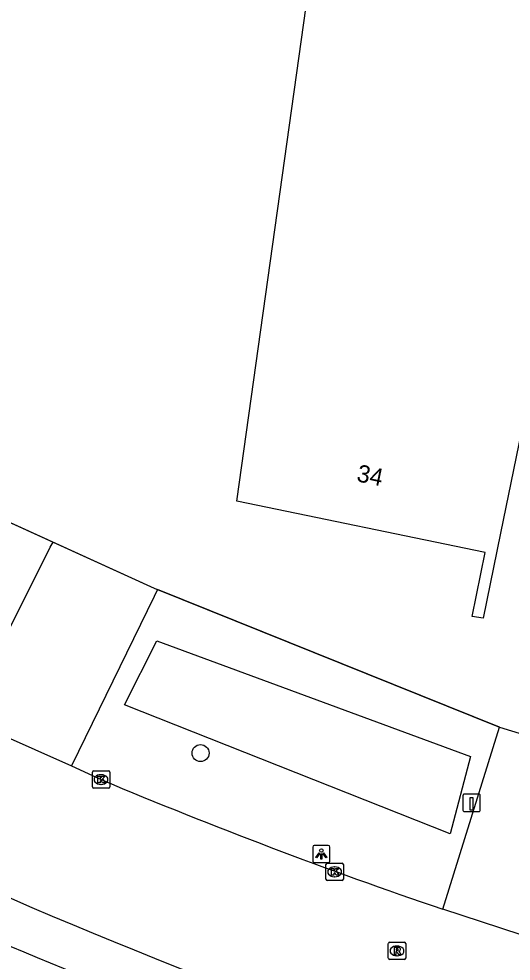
# Model space of a CAD drawing. Extents: x 157692 to 159670, y 381454 to 383289.
# Drawn here: x 158173.9 to 158202.3, y 381831.4 to 381885.7 of the extents above; entities that cross this region are included whole.
import ezdxf

# ---------------------------------------------------------------- set-up
doc = ezdxf.new("R2010")
doc.units = 0
for name, color, linetype in [('IMGEO_Berm_groen', 7, 'Continuous'), ('IMGEO_Boom', 7, 'Continuous'), ('IMGEO_Groenvoorziening', 7, 'Continuous'), ('IMGEO_Hek', 7, 'Continuous'), ('IMGEO_Kolk', 7, 'Continuous'), ('IMGEO_Lichtpunt', 7, 'Continuous'), ('IMGEO_Paal', 7, 'Continuous'), ('IMGEO_Pand', 7, 'Continuous'), ('IMGEO_Pand_nummerreeks', 7, 'Continuous'), ('IMGEO_Rijbaan_lokaal_gesloten', 7, 'Continuous'), ('IMGEO_Rijbaan_lokaal_open', 7, 'Continuous'), ('IMGEO_Rioolput', 7, 'Continuous'), ('IMGEO_Voetpad_open', 7, 'Continuous'), ('IMGEO_Waterloop', 7, 'Continuous')]:
    doc.layers.add(name, color=color, linetype=linetype)

msp = doc.modelspace()

# ---------------------------------------------------------------- linework, layer by layer
at = {"layer": 'IMGEO_Berm_groen'}
msp.add_lwpolyline([(158201.637, 381844.863), (158181.907, 381852.815)], dxfattribs=at)
at = {"layer": 'IMGEO_Boom'}
msp.add_circle((158184.392, 381843.374), 0.489, dxfattribs=at)
at = {"layer": 'IMGEO_Groenvoorziening'}
msp.add_lwpolyline([(158152.635, 381866.121), (158152.79, 381866.076), (158175.894, 381855.545)], dxfattribs=at)
at = {"layer": 'IMGEO_Hek'}
msp.add_lwpolyline([(158152.635, 381866.121), (158152.79, 381866.076), (158181.715, 381852.892), (158201.637, 381844.863)], dxfattribs=at)
at = {"layer": 'IMGEO_Kolk'}
for p, q in [((158178.228, 381842.346), (158179.08, 381842.346)), ((158178.153, 381841.42), (158178.153, 381842.272)), ((158178.641, 381842.126), (158178.666, 381842.126)), ((158179.154, 381842.272), (158179.154, 381841.42)), ((158179.08, 381841.346), (158178.228, 381841.346)), ((158178.664, 381841.566), (158178.639, 381841.566)), ((158191.627, 381836.096), (158191.627, 381836.948)), ((158191.702, 381837.022), (158192.554, 381837.022)), ((158192.628, 381836.948), (158192.628, 381836.096)), ((158192.115, 381836.802), (158192.14, 381836.802)), ((158192.554, 381836.022), (158191.702, 381836.022)), ((158192.138, 381836.242), (158192.113, 381836.242))]:
    msp.add_line(p, q, dxfattribs=at)
for points in [[(158178.228, 381842.346), (158179.08, 381842.346)], [(158178.153, 381841.42), (158178.153, 381842.272)], [(158178.474, 381842.046), (158178.597, 381842.046), (158178.597, 381841.895), (158178.727, 381842.046), (158178.891, 381842.046), (158178.745, 381841.895), (158178.898, 381841.646), (158178.746, 381841.646), (158178.661, 381841.81), (158178.597, 381841.743), (158178.597, 381841.646), (158178.474, 381841.646), (158178.474, 381842.046)], [(158179.154, 381842.272), (158179.154, 381841.42)], [(158179.08, 381841.346), (158178.228, 381841.346)], [(158191.627, 381836.096), (158191.627, 381836.948)], [(158191.702, 381837.022), (158192.554, 381837.022)], [(158192.628, 381836.948), (158192.628, 381836.096)], [(158191.948, 381836.722), (158192.071, 381836.722), (158192.071, 381836.571), (158192.201, 381836.722), (158192.365, 381836.722), (158192.219, 381836.571), (158192.372, 381836.322), (158192.22, 381836.322), (158192.135, 381836.486), (158192.071, 381836.419), (158192.071, 381836.322), (158191.948, 381836.322), (158191.948, 381836.722)], [(158192.554, 381836.022), (158191.702, 381836.022)]]:
    msp.add_lwpolyline(points, dxfattribs=at)
for centre, start, end in [((158178.23, 381842.27), 91.552, 178.448), ((158178.23, 381842.27), 91.552, 178.448), ((158179.078, 381842.27), 1.552, 88.448), ((158179.078, 381842.27), 1.552, 88.448), ((158178.23, 381841.422), 181.552, 268.448), ((158178.23, 381841.422), 181.552, 268.448), ((158179.078, 381841.422), 271.552, 358.448), ((158179.078, 381841.422), 271.552, 358.448), ((158191.704, 381836.946), 91.552, 178.448), ((158191.704, 381836.946), 91.552, 178.448), ((158192.552, 381836.946), 1.552, 88.448), ((158192.552, 381836.946), 1.552, 88.448), ((158191.704, 381836.098), 181.552, 268.448), ((158191.704, 381836.098), 181.552, 268.448), ((158192.552, 381836.098), 271.552, 358.448), ((158192.552, 381836.098), 271.552, 358.448)]:
    msp.add_arc(centre, 0.0765, start, end, dxfattribs=at)
for centre, major_axis, ratio, start_param, end_param in [((158178.64, 381841.846), (-0.387, 0.002), 0.722429, 4.712389, 7.853982), ((158178.665, 381841.846), (-0.39, 0.002), 0.717154, 1.570796, 4.712389), ((158192.114, 381836.522), (-0.387, 0.002), 0.722429, 4.712389, 7.853982), ((158192.139, 381836.522), (-0.39, 0.002), 0.717154, 1.570796, 4.712389)]:
    msp.add_ellipse(centre, major_axis=major_axis, ratio=ratio, start_param=start_param, end_param=end_param, dxfattribs=at)
at = {"layer": 'IMGEO_Lichtpunt'}
for p, q in [((158190.86, 381837.952), (158190.86, 381837.145)), ((158190.86, 381837.952), (158190.86, 381837.145)), ((158191.762, 381838.047), (158190.954, 381838.047)), ((158191.762, 381838.047), (158190.954, 381838.047)), ((158191.856, 381837.145), (158191.856, 381837.952)), ((158191.856, 381837.145), (158191.856, 381837.952)), ((158190.954, 381837.051), (158191.762, 381837.051)), ((158190.954, 381837.051), (158191.762, 381837.051))]:
    msp.add_line(p, q, dxfattribs=at)
for points in [[(158191.234, 381837.616), (158191.273, 381837.588), (158191.085, 381837.326), (158191.047, 381837.353), (158191.234, 381837.616)], [(158191.336, 381837.568), (158191.383, 381837.568), (158191.383, 381837.246), (158191.336, 381837.246), (158191.336, 381837.568)], [(158191.446, 381837.588), (158191.484, 381837.615), (158191.671, 381837.353), (158191.632, 381837.325), (158191.446, 381837.588)]]:
    msp.add_lwpolyline(points, dxfattribs=at)
msp.add_circle((158191.359, 381837.75), 0.0994, dxfattribs=at)
for centre, start, end in [((158190.954, 381837.952), 90, 180), ((158190.954, 381837.952), 90, 180), ((158191.762, 381837.952), 0, 90), ((158191.762, 381837.952), 0, 90), ((158190.954, 381837.145), 180, 270), ((158190.954, 381837.145), 180, 270), ((158191.762, 381837.145), 270, 0), ((158191.762, 381837.145), 270, 360)]:
    msp.add_arc(centre, 0.0946, start, end, dxfattribs=at)
at = {"layer": 'IMGEO_Paal'}
for p, q in [((158199.526, 381840.916), (158199.526, 381840.075)), ((158199.526, 381840.916), (158199.526, 381840.075)), ((158200.442, 381841), (158199.601, 381841)), ((158200.442, 381841), (158199.601, 381841)), ((158200.526, 381840.084), (158200.526, 381840.925)), ((158200.526, 381840.084), (158200.526, 381840.925)), ((158199.61, 381840), (158200.451, 381840)), ((158199.61, 381840), (158200.451, 381840))]:
    msp.add_line(p, q, dxfattribs=at)
msp.add_lwpolyline([(158199.941, 381840.813), (158200.101, 381840.813), (158200.101, 381840.08), (158199.941, 381840.08), (158199.941, 381840.813)], dxfattribs=at)
for centre, start, end in [((158199.604, 381840.922), 92.4484, 184.2845), ((158199.604, 381840.922), 92.4484, 184.2845), ((158200.448, 381840.922), 2.4484, 94.2845), ((158200.448, 381840.922), 2.4484, 94.2845), ((158199.604, 381840.078), 182.4484, 274.2845), ((158199.604, 381840.078), 182.4484, 274.2845), ((158200.448, 381840.078), 272.4484, 4.2845), ((158200.448, 381840.078), 272.4484, 4.2845)]:
    msp.add_arc(centre, 0.0779, start, end, dxfattribs=at)
at = {"layer": 'IMGEO_Pand'}
msp.add_lwpolyline([(158136.166, 381925.258), (158192.825, 381913.715), (158212.684, 381909.652), (158201.697, 381856.053), (158200.693, 381851.154), (158200.049, 381851.25), (158200.81, 381854.948), (158186.49, 381857.896), (158187.182, 381862.848), (158191.444, 381893.334), (158184.121, 381894.823), (158154.699, 381900.804), (158150.089, 381901.741)], dxfattribs=at)
at = {"layer": 'IMGEO_Rijbaan_lokaal_gesloten'}
for points in [[(158170.769, 381845.392), (158176.956, 381842.64)], [(158176.956, 381842.64), (158178.653, 381841.845)], [(158205.116, 381832.151), (158198.373, 381834.361)]]:
    msp.add_lwpolyline(points, dxfattribs=at)
for centre, radius, start, end in [((158296.897, 382123.689), 305.643, 247.2402, 251.19497), ((158293.532, 382111.805), 301.735, 245.58593, 253.34762)]:
    msp.add_arc(centre, radius, start, end, dxfattribs=at)
at = {"layer": 'IMGEO_Rijbaan_lokaal_open'}
for points in [[(158171.542, 381846.928), (158175.726, 381855.243), (158175.894, 381855.545)], [(158175.894, 381855.545), (158181.715, 381852.892), (158181.907, 381852.815)], [(158181.907, 381852.815), (158181.717, 381852.408), (158176.956, 381842.64)], [(158198.373, 381834.361), (158201.637, 381844.863)], [(158201.637, 381844.863), (158208.362, 381842.809), (158208.31, 381842.627)]]:
    msp.add_lwpolyline(points, dxfattribs=at)
at = {"layer": 'IMGEO_Rioolput'}
for p, q in [((158195.223, 381831.537), (158195.223, 381832.389)), ((158195.298, 381832.463), (158196.15, 381832.463)), ((158195.711, 381832.243), (158195.736, 381832.243)), ((158196.224, 381832.389), (158196.224, 381831.537)), ((158196.15, 381831.463), (158195.298, 381831.463)), ((158195.734, 381831.683), (158195.709, 381831.683))]:
    msp.add_line(p, q, dxfattribs=at)
for points in [[(158195.223, 381831.537), (158195.223, 381832.389)], [(158195.298, 381832.463), (158196.15, 381832.463)], [(158195.812, 381832.161), (158195.56, 381832.163), (158195.56, 381831.763)], [(158195.738, 381832.082), (158195.684, 381832.082), (158195.684, 381832.001)], [(158195.684, 381832.001), (158195.736, 381832.001)], [(158196.224, 381832.389), (158196.224, 381831.537)], [(158196.15, 381831.463), (158195.298, 381831.463)], [(158195.56, 381831.763), (158195.684, 381831.763), (158195.684, 381831.925), (158195.695, 381831.925)], [(158195.742, 381831.896), (158195.813, 381831.763), (158195.953, 381831.763), (158195.888, 381831.889)]]:
    msp.add_lwpolyline(points, dxfattribs=at)
for centre, radius, start, end in [((158195.3, 381832.387), 0.0765, 91.552, 178.448), ((158195.3, 381832.387), 0.0765, 91.552, 178.448), ((158195.72, 381832.19), 0.19, 274.7715, 282.9687), ((158195.744, 381831.986), 0.0964, 77.0061, 93.1865), ((158195.758, 381832.043), 0.0378, 276.6634, 79.6772), ((158195.811, 381832.051), 0.109, 350.3612, 89.416), ((158195.809, 381832.051), 0.112, 277.5842, 350.9817), ((158196.148, 381832.387), 0.0765, 1.552, 88.448), ((158196.148, 381832.387), 0.0765, 1.552, 88.448), ((158195.3, 381831.539), 0.0765, 181.552, 268.448), ((158195.3, 381831.539), 0.0765, 181.552, 268.448), ((158195.694, 381831.872), 0.0533, 26.0293, 88.6989), ((158195.793, 381831.836), 0.108, 29.5134, 73.7905), ((158196.148, 381831.539), 0.0765, 271.552, 358.448), ((158196.148, 381831.539), 0.0765, 271.552, 358.448)]:
    msp.add_arc(centre, radius, start, end, dxfattribs=at)
for centre, major_axis, ratio, start_param, end_param in [((158195.71, 381831.963), (-0.387, 0.002), 0.722429, 4.712389, 7.853982), ((158195.735, 381831.963), (-0.39, 0.002), 0.717154, 1.570796, 4.712389)]:
    msp.add_ellipse(centre, major_axis=major_axis, ratio=ratio, start_param=start_param, end_param=end_param, dxfattribs=at)
at = {"layer": 'IMGEO_Voetpad_open'}
for centre, radius, start, end in [((158324.825, 382189.32), 387.854, 244.72884, 248.6019), ((158299.7, 382126.88), 322.874, 244.00529, 248.69973)]:
    msp.add_arc(centre, radius, start, end, dxfattribs=at)
at = {"layer": 'IMGEO_Waterloop'}
msp.add_lwpolyline([(158180.013, 381846.154), (158181.863, 381849.852), (158199.963, 381843.179), (158198.783, 381838.721), (158180.013, 381846.154)], dxfattribs=at)

# ---------------------------------------------------------------- texts
at = {"layer": 'IMGEO_Pand_nummerreeks'}
msp.add_text('34', height=1, rotation=348.369, dxfattribs=at).set_placement((158193.349, 381859.056))

doc.saveas('drawing.dxf')
